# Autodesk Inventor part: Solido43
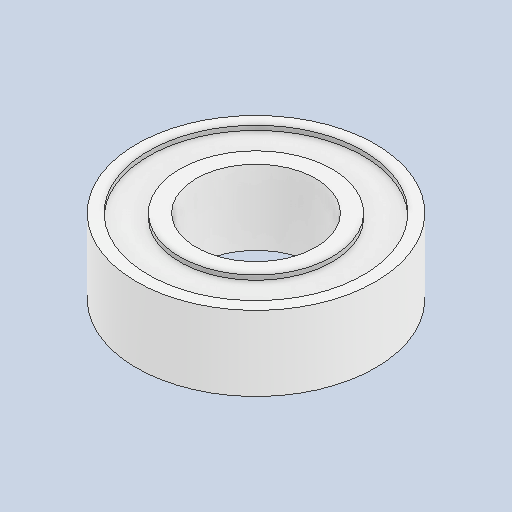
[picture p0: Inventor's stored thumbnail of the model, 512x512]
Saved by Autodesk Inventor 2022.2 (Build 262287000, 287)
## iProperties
Created: 2024-10
Part Number: Solido43
Material: Generico
Document SubType Name: Modeling
Designer: 18907419
Density: 1 g/cm^3
Appearance: Default
Author: 18907419
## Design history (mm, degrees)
feature "Solido43"
node "Solido1"
